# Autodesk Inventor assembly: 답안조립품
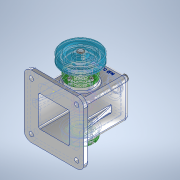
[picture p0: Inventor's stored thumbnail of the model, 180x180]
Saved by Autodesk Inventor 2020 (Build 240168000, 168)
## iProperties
Created: 2022-11
Part Number: 답안조립품
Document SubType Name: Assembly
Designer: USER
Author: USER
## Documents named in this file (17)
- C:\Users\USER\Desktop\721106V1018\답안조립품.iam.iam
- C:\Users\USER\Desktop\721106V1018\본체.ipt.ipt
- C:\Users\USER\Desktop\721106V1018\부시.ipt
- C:\Users\USER\Desktop\721106V1018\편심축.ipt
- C:\Users\USER\Desktop\721106V1018\베어링 6201.ipt
- C:\Users\USER\Desktop\721106V1018\뒤커버.ipt
- C:\Users\USER\Desktop\721106V1018\앞커버.ipt
- C:\Users\USER\Desktop\721106V1018\볼트 M4 x 12.ipt
- C:\Users\USER\Desktop\721106V1018\링크.ipt
- C:\Users\USER\Desktop\721106V1018\슬라이드.ipt
- C:\Users\USER\Desktop\721106V1018\핀 5 x 18.ipt
- C:\Users\USER\Desktop\721106V1018\고정핀 1.2 x 10.ipt
- C:\Users\USER\Desktop\721106V1018\오일실 12 25 7.ipt
- C:\Users\USER\Desktop\721106V1018\키 4 x 4 x 15.ipt
- C:\Users\USER\Desktop\721106V1018\V벨트풀리.ipt
- C:\Users\USER\Desktop\721106V1018\멈춤나사 M3 x 8.ipt
- 본체.ipt
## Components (11 placed, 4 different names)
1. ISO 4762 M4 x 12:1
2. ISO 4762 M4 x 12:2
3. ISO 4762 M4 x 12:3
4. ISO 4762 M4 x 12:4
5. ISO 4762 M4 x 12:5
6. ISO 4762 M4 x 12:6
7. ISO 4762 M4 x 12:7
8. ISO 4762 M4 x 12:8
9. 핀 5 x 18:1
10. 고정핀 1.2 x 10:1
11. V벨트풀리:1
